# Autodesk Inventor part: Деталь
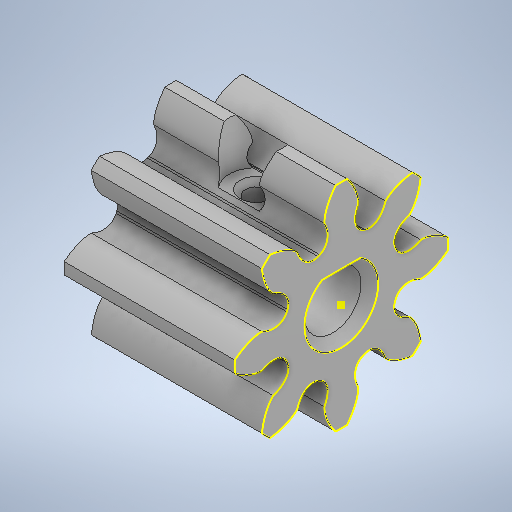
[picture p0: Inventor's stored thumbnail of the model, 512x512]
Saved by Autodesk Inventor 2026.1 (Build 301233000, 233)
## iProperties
Company: UNSPECIFIED
Created: 1900-01
Part Number: Деталь
Material: Типовые
Description: STEP AP203
Document SubType Name: Modeling
Designer: Yury Melnikov
Density: 1 g/cm^3
Appearance: По умолчанию
Sending System: C3D Toolkit
Preprocessor: C3D Converter
Title: Äåòàëü
Author: UNSPECIFIED
Revision Number: ANYUNSPECIFIED
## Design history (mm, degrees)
node "Исправленная геометрия1"
  sketch "3D эскиз1"
  node "3D эскиз2"
  node "3D эскиз3"
  node "3D эскиз4"
  sketch "3D эскиз5"
  node "3D эскиз6"
feature "БазТело1"
sketch "Эскиз1"
  geometry: L1 (-1.549, 2.15)-(1.549, 2.15); A1 r 2.65 centre (0, 0) between (-1.549, 2.15) and (1.549, 2.15); 1 further point
  constraints: 2 end point, 2 point on circle, 1 centre point, 1 coincident, 1 horizontal
  dimensions: "d0" = 5.3 diameter of A1; "d1" = 4.8 dimension on A1 L1
extrude "Выдавливание1" cut sketch "Эскиз1" distance "d2" = 20; taper "d3" = 0 deg
sketch "Эскиз2"
  geometry: L1 (-16, 8.992)-(0, 8.992) reference; C1 r 1 at (-8, 1.549); 2 further points
  constraints: 1 centre point, 1 horizontal alignment, 1 midpoint, 1 vertical alignment
  dimensions: "d4" = 2 diameter of C1
extrude "Выдавливание2" cut sketch "Эскиз2" distance "d5" = 20; taper "d6" = 0 deg
node "РабПлоскость1"
sketch "Эскиз3"
  geometry: C1 r 1 at (-8, 1.549) reference; C2 r 2.5 at (-8, 1.549); 5 further points
  constraints: 2 horizontal alignment, 2 vertical alignment, 1 centre point, 1 coincident
  dimensions: "d8" = 5 diameter of C2
extrude "Выдавливание3" cut sketch "Эскиз3" distance "d9" = 20; taper "d10" = 0 deg
chamfer "Фаска1" distance "d11" = 0.5; stored, may be unused: second distance "d12" = 2, angle "d13" = 45 deg
chamfer "Фаска2" distance "d14" = 0.8; stored, may be unused: second distance "d15" = 2, angle "d16" = 45 deg
sketch "Эскиз4"
  geometry: L1 (1.789, 2.95)-(-1.789, 2.95) reference; A1 r 10 centre (0, 0) between (-6.678, 7.443) and (-7.443, 6.678) reference; A2 r 5.5 centre (0, 0) between (-5.047, 2.186) and (-5.115, 2.023) reference; A3 r 10 centre (0, 0) between (-9.985, 0.541) and (-9.985, -0.541) reference; A4 r 5.5 centre (0, 0) between (-5.115, -2.023) and (-5.047, -2.186) reference; A5 r 10 centre (0, 0) between (-7.443, -6.678) and (-6.678, -7.443) reference; A6 r 5.5 centre (0, 0) between (-2.186, -5.047) and (-2.023, -5.115) reference; A7 r 10 centre (0, 0) between (-0.541, -9.985) and (0.541, -9.985) reference; A8 r 5.5 centre (0, 0) between (2.023, -5.115) and (2.186, -5.047) reference; A9 r 10 centre (0, 0) between (6.678, -7.443) and (7.443, -6.678) reference; A10 r 5.5 centre (0, 0) between (5.047, -2.186) and (5.115, -2.023) reference; A11 r 10 centre (0, 0) between (9.985, -0.541) and (9.985, 0.541) reference; A12 r 5.5 centre (0, 0) between (5.115, 2.023) and (5.047, 2.186) reference; A13 r 10 centre (0, 0) between (7.443, 6.678) and (6.678, 7.443) reference; A14 r 5.5 centre (0, 0) between (2.186, 5.047) and (2.023, 5.115) reference; A15 r 10 centre (0, 0) between (0.541, 9.985) and (-0.541, 9.985) reference; A16 r 5.5 centre (0, 0) between (-2.023, 5.115) and (-2.186, 5.047) reference; A17 r 3.45 centre (0, 0) between (-1.789, 2.95) and (1.789, 2.95) reference; 17 further points
  constraints: 32 other
  node "Спроецированная петля2"
node "Твердое тело1"
node "Спроецированная петля1"
other parameters: "d7" = -3.25
